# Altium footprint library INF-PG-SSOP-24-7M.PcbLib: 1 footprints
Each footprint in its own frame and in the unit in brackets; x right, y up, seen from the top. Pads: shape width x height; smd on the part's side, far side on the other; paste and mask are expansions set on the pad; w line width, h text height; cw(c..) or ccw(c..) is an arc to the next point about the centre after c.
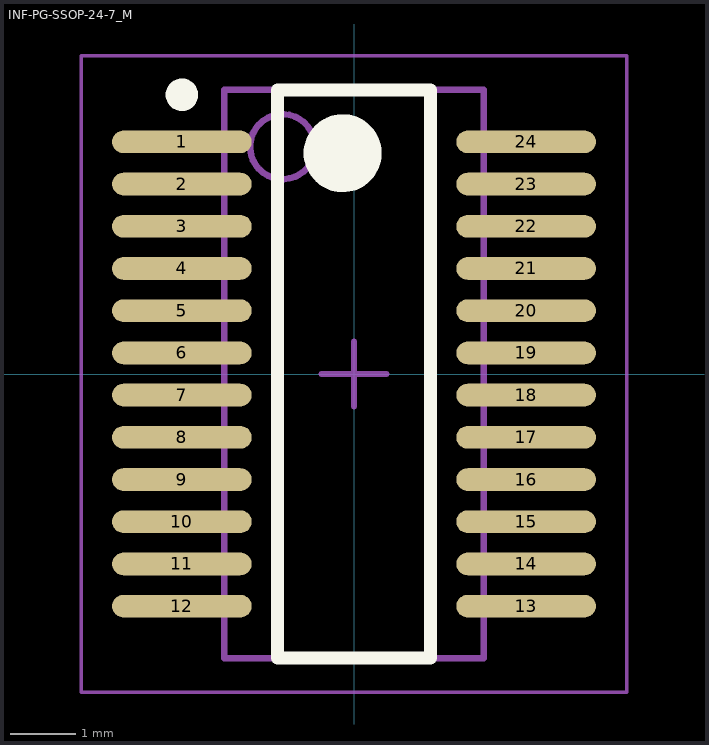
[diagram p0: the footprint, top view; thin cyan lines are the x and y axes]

## INF-PG-SSOP-24-7_M [mm] "SOP, 24-Leads, Body 8.65x3.9mm, Pitch 0.65mm, IPC Low Density"
height 1.75
pads (24):
  oval 2.15x0.35 smd: 1(-2.65,3.575) 2(-2.65,2.925) 3(-2.65,2.275) 4(-2.65,1.625) 5(-2.65,0.975) 6(-2.65,0.325) 7(-2.65,-0.325) 8(-2.65,-0.975) 9(-2.65,-1.625) 10(-2.65,-2.275) 11(-2.65,-2.925) 12(-2.65,-3.575) 13(2.65,-3.575) 14(2.65,-2.925) 15(2.65,-2.275) 16(2.65,-1.625) 17(2.65,-0.975) 18(2.65,-0.325) 19(2.65,0.325) 20(2.65,0.975) 21(2.65,1.625) 22(2.65,2.275) 23(2.65,2.925) 24(2.65,3.575)
Top Overlay:
  circle w0.6: c-0.175,3.4 r0.3
  circle w0.25: c-2.65,4.3 r0.125
  lines w0.2: -1.175,-4.375 1.175,-4.375 1.175,4.375 -1.175,4.375 -1.175,-4.375
Mechanical 13:
  circle w0.1: c-1.1,3.5 r0.5
  lines w0.1: -2,-4.375 2,-4.375 2,4.375 -2,4.375 -2,-4.375
Mechanical 15:
  lines w0.05: -4.2,-4.9 4.2,-4.9 4.2,4.9 -4.2,4.9 -4.2,-4.9
  lines w0.1: -0.5,0 0.5,0 ; 0,-0.5 0,0.5
3D body: height 1.75, standoff 0.11, extent -2,-4.375 2,4.375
